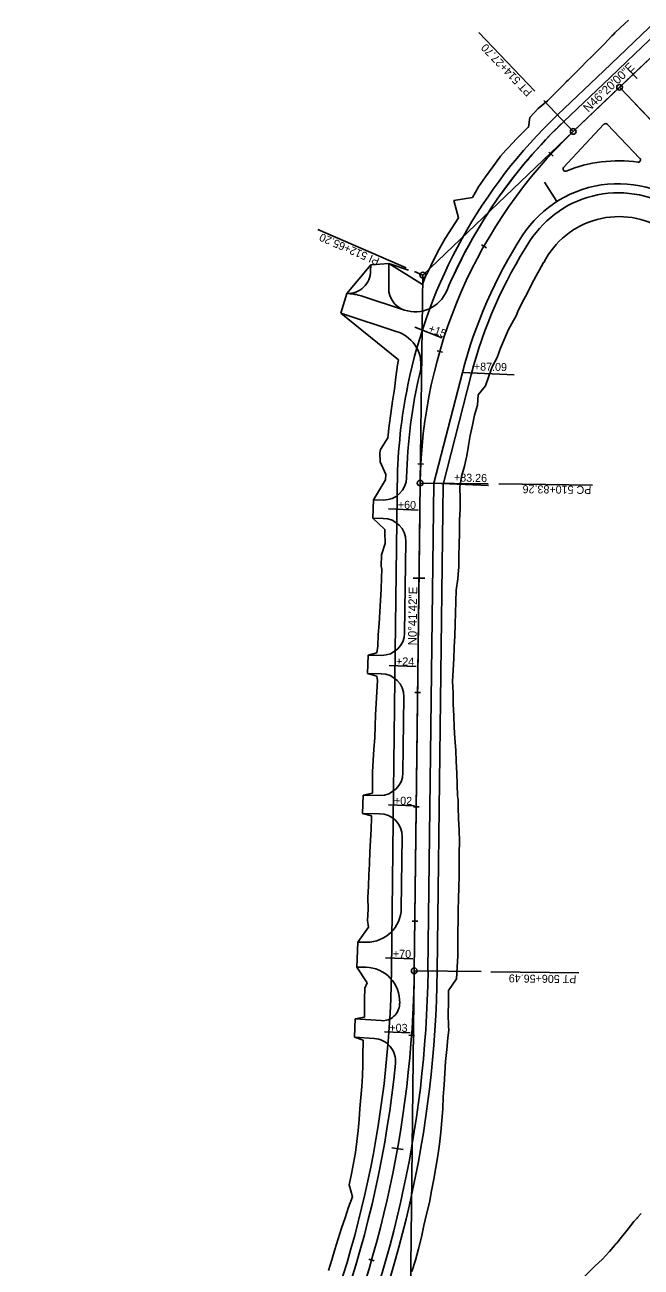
# Model space of a CAD drawing. Extents: x 1300404 to 1323571, y 237813 to 252077.
# Drawn here: x 1309632 to 1310171, y 240634 to 241720 of the extents above; entities that cross this region are included whole.
import ezdxf

# ---------------------------------------------------------------- set-up
doc = ezdxf.new("R2010")
doc.units = 0
for name, color, linetype in [('R_Const Limits', 7, 'Continuous'), ('R_Draft', 7, 'Continuous'), ('R_Horz Alg Annot', 7, 'Continuous'), ('R_Horz Alg Annot Leader', 7, 'Continuous'), ('R_Horz Alg Major Ticks', 7, 'Continuous'), ('R_Horz Alg Minor Ticks', 7, 'Continuous'), ('R_Horz Alg Tangents', 7, 'Continuous'), ('R_Horz Alg Tangents Text', 7, 'Continuous'), ('R_Lane Edge', 7, 'Continuous'), ('R_No Plot', 7, 'Continuous'), ('R_Proposed', 7, 'Continuous'), ('R_Shoulder', 7, 'Continuous'), ('R_Temp Easement', 7, 'Continuous'), ('T_Drafting', 7, 'Continuous')]:
    doc.layers.add(name, color=color, linetype=linetype)

msp = doc.modelspace()

# ---------------------------------------------------------------- linework, layer by layer
at = {"layer": 'R_Const Limits'}
for p, q in [((1309934.2, 241510.4), (1309913.4, 241485.3)), ((1309950.2, 241511.6), (1309934.2, 241510.4)), ((1309979.4, 241493.2), (1309950.2, 241511.6)), ((1309913.4, 241485.3), (1309908.2, 241468.1)), ((1309958.4, 241427.3), (1309908.2, 241468.1)), ((1309936.7, 241304.8), (1309947.1, 241322.5)), ((1309936.1, 241288.8), (1309936.7, 241304.8)), ((1309936.1, 241288.8), (1309946.5, 241278.9)), ((1309931.9, 241168.9), (1309939.6, 241171)), ((1309931.3, 241152.9), (1309931.9, 241168.9)), ((1309931.3, 241152.9), (1309939.6, 241150.7)), ((1309927, 241030.4), (1309927.6, 241046.4)), ((1309927.6, 241046.4), (1309935.7, 241048.3)), ((1309927, 241030.4), (1309935, 241028.4)), ((1309923, 240918), (1309932.3, 240931)), ((1309922.2, 240896), (1309923, 240918)), ((1309922.2, 240896), (1309931.1, 240882.4)), ((1309920.1, 240834.8), (1309920.6, 240850.8)), ((1309920.6, 240850.8), (1309928.7, 240852.3)), ((1309920.1, 240834.8), (1309927.6, 240832.3))]:
    msp.add_line(p, q, dxfattribs=at)
for points in [[(1309979.4, 241493.2), (1309980, 241495), (1309982.2, 241500.5), (1309984.4, 241504.8), (1309989.1, 241514.5), (1309994, 241524.1), (1309999.4, 241533.4), (1310005.1, 241542.6), (1310011, 241551.5), (1310007, 241566.7), (1310023.1, 241569.3), (1310028.5, 241578.6), (1310034.6, 241587.4), (1310040.9, 241596.1), (1310047.2, 241604.8), (1310047.8, 241605.5), (1310052.5, 241610.8), (1310054.4, 241612.8), (1310061.7, 241620.7), (1310069.4, 241628.2), (1310072, 241630.8), (1310072.2, 241630.9), (1310073.3, 241639.3), (1310080.6, 241647.2), (1310088.8, 241654.1), (1310095.9, 241661.1), (1310103, 241668.2), (1310105.5, 241670.8), (1310106.9, 241672.2), (1310110.1, 241675.3), (1310117.1, 241682.4), (1310124.1, 241689.5), (1310126.7, 241692), (1310126.7, 241692), (1310131.3, 241696.5), (1310138.3, 241703.6), (1310145.2, 241710.9), (1310146.4, 241712), (1310147.8, 241713.4), (1310152.4, 241717.8), (1310159.7, 241724.7)], [(1310085.4, 241512.4), (1310083.2, 241508.7), (1310078.8, 241501), (1310074.8, 241493.2), (1310071, 241485.3), (1310066.8, 241477.6), (1310063, 241469.6), (1310061.4, 241466), (1310059.1, 241461.8), (1310054.6, 241454), (1310051.3, 241445.8), (1310047.8, 241437.7), (1310044.9, 241429.4), (1310040.5, 241421.4), (1310037.5, 241413), (1310034.6, 241404.5), (1310028.3, 241396.8), (1310027.5, 241387.7), (1310025, 241379), (1310023.1, 241370.2), (1310021.1, 241361.3), (1310019.6, 241352.4), (1310018.2, 241343.4), (1310017.8, 241341), (1310016.1, 241334.4), (1310013.6, 241325.3), (1310012.1, 241315.9), (1310012.5, 241305.9), (1310012.4, 241295.9), (1310012.2, 241293.3), (1310012, 241285.9), (1310011.9, 241275.9), (1310011.6, 241265.9), (1310011.2, 241255.9), (1310011.3, 241245.9), (1310011, 241243.3), (1310010.4, 241235.9), (1310009, 241226), (1310008.7, 241216), (1310008.5, 241206), (1310008.1, 241196), (1310007.7, 241186), (1310007.3, 241176), (1310006.8, 241166), (1310006.3, 241156), (1310005.8, 241146), (1310006.3, 241136), (1310006.4, 241126), (1310006.9, 241116), (1310007.3, 241106), (1310007.9, 241096), (1310008.6, 241085.9), (1310009.1, 241075.9), (1310009.6, 241065.9), (1310009.9, 241055.9), (1310010.1, 241045.9), (1310010.7, 241042.4), (1310010.7, 241042.4), (1310010.8, 241035.9), (1310011.1, 241025.9), (1310011.7, 241015.9), (1310011.9, 241005.9), (1310011.7, 240995.9), (1310011.6, 240985.9), (1310011.6, 240985.3), (1310011.5, 240975.9), (1310011.4, 240965.9), (1310011, 240955.9), (1310010.8, 240945.9), (1310010.6, 240935.9), (1310010.5, 240928.1), (1310010.5, 240925.9), (1310010.5, 240915.9), (1310010.3, 240905.9), (1310009.8, 240895.9), (1310009.3, 240885.7), (1310002.2, 240875.5), (1310002.2, 240865.2), (1310002.1, 240854.8), (1310002.3, 240844.5), (1310002.6, 240840.8), (1310001.8, 240834.2), (1310000.7, 240823.9), (1309999.7, 240813.6), (1309999, 240803.3), (1309998.4, 240793), (1309997.6, 240782.6), (1309997.4, 240772.2), (1309996.5, 240761.9), (1309995.5, 240751.6), (1309994.4, 240741.2), (1309992.9, 240731), (1309991.2, 240720.7), (1309989.4, 240710.5), (1309987.5, 240700.3), (1309985.5, 240690.1), (1309983.1, 240680), (1309980.8, 240669.9), (1309978.5, 240659.8), (1309976, 240649.7), (1309973.3, 240639.7), (1309970.3, 240629.7)], [(1309947.1, 241322.5), (1309947.4, 241327.2), (1309942.6, 241338.1), (1309942.3, 241346.1), (1309942.7, 241349), (1309949.1, 241359.2), (1309950.3, 241369.9), (1309951.8, 241380.5), (1309953.4, 241391.1), (1309954.9, 241401.7), (1309956.3, 241412.3), (1309957.8, 241423), (1309958.4, 241427.3)], [(1309939.6, 241171), (1309940.4, 241176.8), (1309940.9, 241186.8), (1309941.5, 241196.8), (1309942.1, 241206.8), (1309942.8, 241216.8), (1309943.3, 241226.8), (1309943.8, 241236.7), (1309944, 241244.1), (1309943.5, 241246.8), (1309943.7, 241256.7), (1309946.8, 241266.7), (1309946.5, 241276.7), (1309946.5, 241278.9)], [(1309935.7, 241048.3), (1309935.7, 241056.8), (1309935.8, 241066.8), (1309936.5, 241076.8), (1309937.1, 241086.8), (1309937.8, 241096.8), (1309938.2, 241106.8), (1309938.5, 241116.8), (1309939, 241126.8), (1309939.5, 241136.8), (1309940.2, 241146.8), (1309939.6, 241150.7)], [(1309932.3, 240931), (1309931.3, 240936.9), (1309932.1, 240946.9), (1309931.8, 240956.9), (1309932.3, 240966.9), (1309932.7, 240976.9), (1309933.3, 240986.2), (1309933.3, 240986.9), (1309933.6, 240996.9), (1309934, 241006.8), (1309934.6, 241016.8), (1309935, 241026.8), (1309935, 241028.4)], [(1309928.7, 240852.3), (1309928.8, 240858.5), (1309928.8, 240868.1), (1309929.2, 240877.6), (1309931.1, 240882.4)], [(1309897.2, 240630.7), (1309900.1, 240639.9), (1309903, 240649.1), (1309905.7, 240658.4), (1309908.6, 240667.6), (1309911.9, 240676.7), (1309914.7, 240686), (1309918.2, 240695.1), (1309915.3, 240705.7), (1309917.4, 240715.1), (1309919.2, 240724.5), (1309920.8, 240734), (1309922.1, 240743.6), (1309923.2, 240753.1), (1309924, 240762.8), (1309924.7, 240772.4), (1309925.6, 240781.9), (1309926.6, 240791.5), (1309927.2, 240801), (1309927.4, 240810.7), (1309927.3, 240820.3), (1309927.5, 240829.9), (1309927.6, 240832.3)], [(1310136.5, 240640.4), (1310136.5, 240640.4), (1310139.7, 240643.9), (1310142.9, 240647.4), (1310146.1, 240651), (1310148, 240653.2), (1310148.6, 240653.9), (1310149.3, 240654.7), (1310152.4, 240658.3), (1310158.4, 240665.8), (1310164.4, 240673.4), (1310167.2, 240676.5), (1310167.6, 240676.9), (1310170.2, 240679.8), (1310170.8, 240680.5)], [(1310032.4, 240539.4), (1310035.6, 240545.7), (1310042, 240553.6), (1310050.3, 240559.3), (1310056.7, 240567.2), (1310065, 240572.9), (1310072.8, 240579.2), (1310080, 240586.1), (1310086.9, 240593.5), (1310094.4, 240600.1), (1310101.6, 240607), (1310105.2, 240610.4), (1310108.9, 240613.8), (1310116.3, 240620.6), (1310123.4, 240627.6), (1310130.6, 240634.6), (1310136.5, 240640.4), (1310136.5, 240640.4)]]:
    msp.add_lwpolyline(points, dxfattribs=at)
msp.add_arc((1310151.3, 241478.8), 73.9, 56.9485, 152.9452, dxfattribs=at)
at = {"layer": 'R_Draft'}
msp.add_line((1309989.5, 241319.5), (1310014.4, 241416.3), dxfattribs=at)
for centre, radius, start, end in [((1310150.7, 241481.5), 100, 43.6667, 147.1004), ((1310409.9, 241314.4), 408.4, 147.1626, 165.5481)]:
    msp.add_arc(centre, radius, start, end, dxfattribs=at)
at = {"layer": 'R_Horz Alg Annot Leader'}
for points in [[(1310077.7, 241662.4), (1310028.7, 241713.7)], [(1310111.3, 241627.2), (1310085.5, 241654.2)], [(1309965.1, 241507.9), (1309888, 241541.4)], [(1309979.7, 241501.5), (1309972.5, 241504.7)], [(1309996.5, 241446.5), (1309972.7, 241456)], [(1310059.7, 241414.3), (1310014.4, 241416.3)], [(1309977.5, 241319.6), (1310037, 241318.9)], [(1310037.1, 241317.4), (1309989.5, 241319.5)], [(1310046.3, 241318.8), (1310128.2, 241317.8)], [(1309975.7, 241296), (1309949.9, 241297.1)], [(1309974.1, 241159), (1309950.3, 241160)], [(1309972.6, 241037.1), (1309949.8, 241038.1)], [(1309971, 240903.2), (1309947.2, 240904.3)], [(1310030.7, 240892.1), (1309972.3, 240892.9)], [(1310116.1, 240891.1), (1310039.2, 240892)], [(1309968.6, 240838.5), (1309946.2, 240839.4)]]:
    msp.add_lwpolyline(points, dxfattribs=at)
at = {"layer": 'R_Horz Alg Major Ticks'}
for points in [[(1310160.2, 241680.7), (1310167.1, 241673.5)], [(1310155.4, 241669.2), (1310148.2, 241662.3)], [(1309971.5, 241236.4), (1309981.5, 241236.3)], [(1309952.7, 240738.1), (1309962.6, 240736.4)]]:
    msp.add_lwpolyline(points, dxfattribs=at)
at = {"layer": 'R_Horz Alg Minor Ticks'}
for points in [[(1310090.1, 241609.1), (1310093.8, 241605.7)], [(1310031, 241527.9), (1310035.4, 241525.5)], [(1309992.2, 241435.4), (1309997, 241434)], [(1309975.5, 241336.5), (1309980.5, 241336.2)], [(1309972.8, 241136.4), (1309977.8, 241136.3)], [(1309971.6, 241036.4), (1309976.6, 241036.3)], [(1309970.4, 240936.4), (1309975.4, 240936.3)], [(1309967.5, 240836.6), (1309972.5, 240836.3)], [(1309932.6, 240640.6), (1309937.4, 240639.2)]]:
    msp.add_lwpolyline(points, dxfattribs=at)
at = {"layer": 'R_Horz Alg Tangents'}
for p, q in [((1309979.7, 241501.5), (1310111.3, 241627.2)), ((1309977.5, 241319.6), (1309979.7, 241501.5)), ((1309967.2, 240465.5), (1309972.3, 240892.9))]:
    msp.add_line(p, q, dxfattribs=at)
at = {"layer": 'R_Lane Edge'}
for p, q in [((1310165.2, 241695.2), (1310189.6, 241718.4)), ((1310143.5, 241674.4), (1310165.2, 241695.2)), ((1310103.1, 241635.8), (1310143.5, 241674.4)), ((1310102.9, 241595.7), (1310138.2, 241633.5)), ((1310141.1, 241633.5), (1310169.6, 241603.6)), ((1309934.1, 241505.1), (1309934.2, 241510.4)), ((1309950, 241490.1), (1309950.2, 241511.6)), ((1309908.2, 241468.1), (1309913.4, 241485.3)), ((1309913.4, 241485.3), (1309914.8, 241485.3)), ((1309925.9, 241483.3), (1309963.7, 241470.9)), ((1309908.2, 241468.1), (1309957.5, 241451.9)), ((1309989.5, 241319.5), (1310014.4, 241416.3)), ((1309984.3, 240892.7), (1309989.5, 241319.5)), ((1309936.7, 241304.8), (1309936.1, 241288.8)), ((1309936.7, 241304.8), (1309945.4, 241304.7)), ((1309936.1, 241288.8), (1309945.1, 241288.7)), ((1309963.9, 241188.5), (1309964.9, 241268.5)), ((1309931.9, 241168.9), (1309931.3, 241152.9)), ((1309931.9, 241168.9), (1309943.7, 241168.8)), ((1309931.3, 241152.9), (1309943.5, 241152.8)), ((1309962.4, 241066), (1309963.2, 241132.5)), ((1309927.6, 241046.4), (1309927, 241030.4)), ((1309927.6, 241046.4), (1309942.2, 241046.3)), ((1309927, 241030.4), (1309942, 241030.3)), ((1309961, 240947.5), (1309961.8, 241010)), ((1309922.2, 240896), (1309923, 240918)), ((1309923, 240918), (1309930.6, 240917.9)), ((1309922.2, 240896), (1309930, 240895.9)), ((1309920.1, 240834.8), (1309920.6, 240850.8)), ((1309920.6, 240850.8), (1309943.5, 240849.3)), ((1309920.1, 240834.8), (1309937.3, 240833.7))]:
    msp.add_line(p, q, dxfattribs=at)
for centre, radius, start, end in [((1310409.9, 241314.4), 444.4, 133.6667, 157.0383), ((1310409.9, 241314.4), 444.4, 133.6667, 154.9082), ((1310139.7, 241632.1), 2, 43.6667, 136.9114), ((1310104.4, 241594.4), 2, 136.9114, 292.3053), ((1310150.7, 241481.5), 120, 81.7713, 112.3053), ((1310168.2, 241602.3), 2, 261.7713, 43.6667), ((1310150.7, 241481.5), 100, 43.6667, 147.1004), ((1310409.9, 241314.4), 408.4, 147.1626, 165.5481), ((1309914.1, 241505.3), 20, 268.0911, 359.4321), ((1309970, 241489.9), 20, 179.4321, 251.8748), ((1309973.1, 241499.4), 30, 251.8748, 337.0383), ((1309913.5, 241445.3), 40, 71.8748, 88.0911), ((1309948.2, 241423.4), 30, 346.7116, 71.8748), ((1310409.9, 241314.4), 444.4, 166.7113, 178.7204), ((1309945.6, 241324.7), 20, 269.305, 358.7204), ((1309944.9, 241268.7), 20, 359.305, 89.305), ((1309943.9, 241188.8), 20, 269.305, 359.305), ((1309943.2, 241132.8), 20, 359.305, 89.305), ((1309942.4, 241066.3), 20, 269.305, 359.305), ((1309941.8, 241010.3), 20, 359.305, 89.305), ((1309931, 240947.9), 30, 269.305, 359.305), ((1309017.5, 240904.4), 966.9, 311.0808, 359.305), ((1309929.6, 240865.9), 30, 357.5799, 89.305), ((1309944.5, 240864.2), 15, 266.096, 357.5163), ((1309017.5, 240904.4), 942.9, 357.5163, 357.5799), ((1309935.9, 240813.7), 20, 354.3575, 86.096), ((1309050.1, 241631.1), 1520.4, 311.1667, 327.8054), ((1309017.5, 240904.4), 942.9, 327.4472, 354.3575)]:
    msp.add_arc(centre, radius, start, end, dxfattribs=at)
at = {"layer": 'R_No Plot'}
msp.add_line((1310086.3, 241582.8), (1310097.1, 241565.9), dxfattribs=at)
at = {"layer": 'R_Proposed'}
for p, q in [((1310111.3, 241627.2), (1310197.9, 241709.8)), ((1310111.3, 241627.2), (1310197.9, 241709.8)), ((1310111.3, 241627.2), (1310197.9, 241709.8)), ((1310151.8, 241665.8), (1310197.9, 241709.8)), ((1310111.3, 241627.2), (1310151.8, 241665.8)), ((1310151.8, 241665.8), (1311952.6, 239779.2)), ((1310165.6, 241651.3), (1311952.6, 239779.1)), ((1310165.6, 241651.3), (1311952.6, 239779.1)), ((1309977.4, 241402.4), (1309977.4, 241402.4)), ((1309972.3, 240892.9), (1309977.5, 241319.6)), ((1309972.3, 240892.9), (1309977.5, 241319.6)), ((1309972.3, 240892.9), (1309977.2, 241291.6)), ((1309972.3, 240892.9), (1309977.2, 241291.6)), ((1309972.3, 240892.9), (1309977.2, 241291.6))]:
    msp.add_line(p, q, dxfattribs=at)
for centre in [(1310151.8, 241665.8), (1310111.3, 241627.2), (1309979.7, 241501.5), (1309977.5, 241319.6), (1309972.3, 240892.9)]:
    msp.add_circle(centre, 2.5, dxfattribs=at)
for centre, radius, start, end in [((1310409.9, 241314.4), 432.4, 133.6667, 179.305), ((1309017.5, 240904.4), 954.9, 311.0808, 359.305), ((1309050.1, 241631.1), 1527.9, 311.1667, 327.8054), ((1309050.1, 241631.1), 1527.9, 311.1667, 327.8054)]:
    msp.add_arc(centre, radius, start, end, dxfattribs=at)
at = {"layer": 'R_Shoulder'}
for p, q in [((1310138, 241680.2), (1310184.1, 241724.2)), ((1310097.5, 241641.6), (1310138, 241680.2)), ((1309997.5, 241318.4), (1310022.2, 241414.3)), ((1309957.4, 241308.6), (1309957.5, 241319.8)), ((1309992.3, 240892.6), (1309997.5, 241318.4)), ((1309955.7, 241172.6), (1309957.4, 241308.6)), ((1309954.2, 241050.1), (1309955.7, 241172.6)), ((1309952.3, 240893.1), (1309954.2, 241050.1))]:
    msp.add_line(p, q, dxfattribs=at)
for centre, radius, start, end in [((1310409.9, 241314.4), 452.4, 133.6667, 168.3977), ((1310150.7, 241481.5), 92, 55.4654, 147.1828), ((1310409.9, 241314.4), 400.4, 147.1633, 165.5481), ((1310409.9, 241314.4), 452.4, 168.3977, 179.305), ((1309017.5, 240904.4), 934.9, 311.0808, 359.305), ((1309017.5, 240904.4), 974.9, 311.0808, 359.305), ((1309050.1, 241631.1), 1514.4, 311.1667, 327.8054)]:
    msp.add_arc(centre, radius, start, end, dxfattribs=at)
at = {"layer": 'R_Temp Easement'}
msp.add_line((1309950.1, 241511.6), (1309967.3, 241505.7), dxfattribs=at)
at = {"layer": 'T_Drafting'}
msp.add_arc((1310409.9, 241314.4), 432.4, 133.6667, 179.305, dxfattribs=at)

# ---------------------------------------------------------------- texts
at = {"layer": 'R_Horz Alg Annot'}
for s, rotation, p in [('PT 514+27.70', 133.6667, (1310075.9, 241661.9)), ('PI 512+65.20', 156.4858, (1309942.6, 241516.1)), ('+15', 339.5652, (1309984, 241452.1)), ('+87.09', 358.8014, (1310024.4, 241418.1)), ('+83.26', 358.8014, (1310007, 241321)), ('PC 510+83.26', 179.305, (1310127.2, 241317)), ('+60', 358.8014, (1309957.9, 241297.2)), ('+24', 358.8014, (1309956.3, 241160.2)), ('+02', 358.8014, (1309954.5, 241038.3)), ('+70', 358.8014, (1309953.6, 240904.4)), ('PT 506+56.49', 179.305, (1310114.1, 240889)), ('+03', 358.8014, (1309950.5, 240839.7))]:
    msp.add_text(s, height=7, rotation=rotation, dxfattribs=at).set_placement(p)
at = {"layer": 'R_Horz Alg Tangents Text'}
for s, rotation, p in [('N46%%d20\'00"E', 43.6667, (1310124.4, 241643.5)), ('N0%%d41\'42"E', 89.305, (1309974.3, 241177.5))]:
    msp.add_text(s, height=7.5, rotation=rotation, dxfattribs=at).set_placement(p)

doc.saveas('drawing.dxf')
